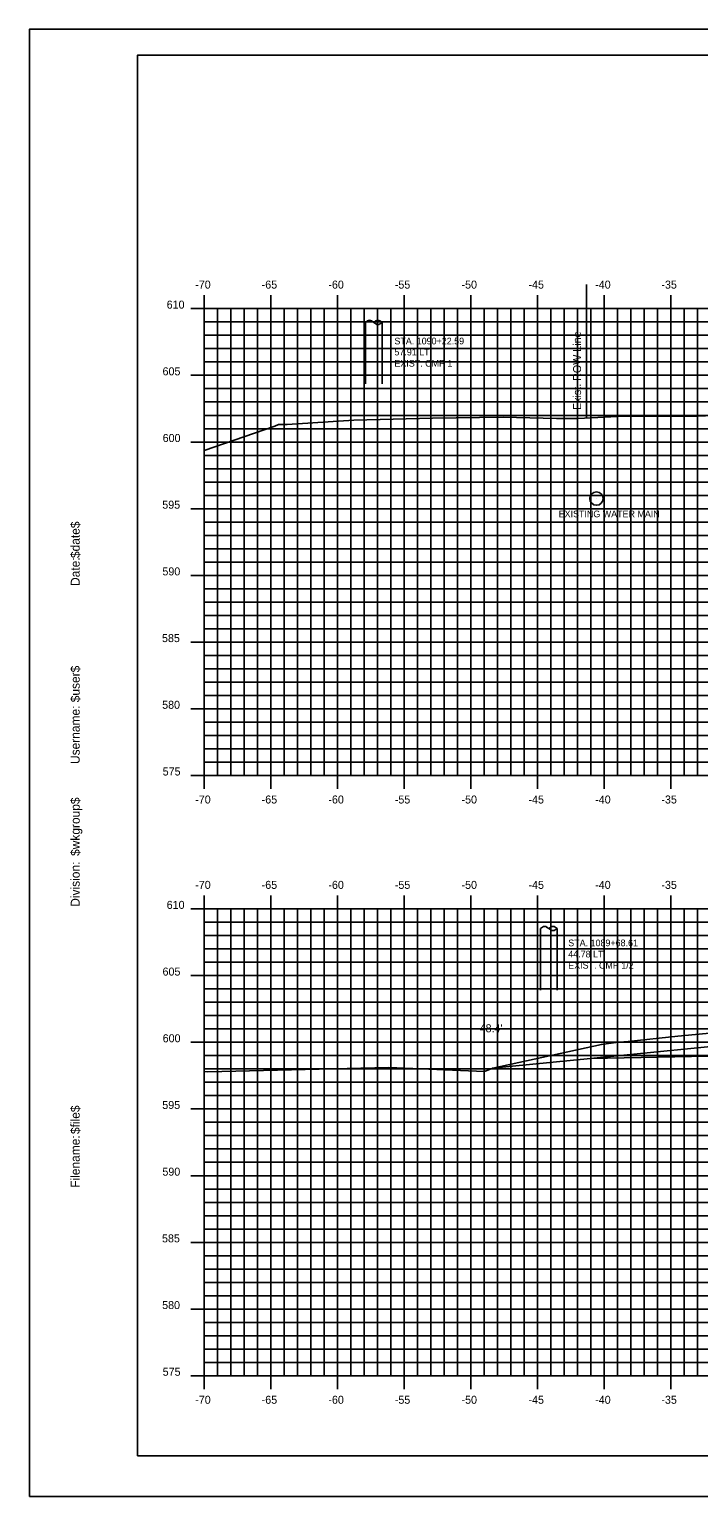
# Model space of a CAD drawing. Extents: x 1073421 to 1073591, y 779716 to 779826.
# Drawn here: x 1073420.9 to 1073471, y 779715.6 to 779825.6 of the extents above; entities that cross this region are included whole.
import ezdxf

# ---------------------------------------------------------------- set-up
doc = ezdxf.new("R2010")
doc.units = 0
for name, color, linetype in [('BORDER', 7, 'Continuous'), ('D_Roadway_SlopeLines', 7, 'Continuous'), ('D_Roadway_SubGrade', 7, 'Continuous'), ('D_Text_Monospaced', 7, 'Continuous'), ('D_Text_Standard', 7, 'Continuous'), ('E_ROW_Line', 7, 'Continuous'), ('Existing Water Main', 7, 'Continuous'), ('H_V ANNOTATION', 7, 'Continuous'), ('MAJOR', 7, 'Continuous'), ('MINOR', 7, 'Continuous'), ('PLOT BOUNDARY', 7, 'Continuous'), ('S_Roadway_Centerline', 7, 'Continuous'), ('S_Utilities_Pole_Joint', 7, 'Continuous'), ('S_Utilities_Pole_Power', 7, 'Continuous')]:
    doc.layers.add(name, color=color, linetype=linetype)

msp = doc.modelspace()

# ---------------------------------------------------------------- linework, layer by layer
at = {"layer": 'BORDER'}
msp.add_lwpolyline([(1073428.96, 779718.71), (1073588.96, 779718.71), (1073588.96, 779823.71), (1073428.96, 779823.71)], close=True, dxfattribs=at)
at = {"layer": 'D_Roadway_SlopeLines'}
msp.add_lwpolyline([(1073462.92, 779748.5), (1073455.55, 779747.76)], dxfattribs=at)
at = {"layer": 'D_Roadway_SubGrade'}
msp.add_lwpolyline([(1073491.96, 779750.83), (1073487.96, 779750.67), (1073487.96, 779751), (1073462.92, 779748.5), (1073491.96, 779749.08), (1073491.96, 779750.83)], close=True, dxfattribs=at)
at = {"layer": 'E_ROW_Line'}
msp.add_line((1073462.62, 779796.51), (1073462.62, 779806.51), dxfattribs=at)
msp.add_line((1073462.62, 779796.51), (1073462.62, 779806.51), dxfattribs=at)
at = {"layer": 'Existing Water Main'}
msp.add_lwpolyline([(1073463.37, 779790.47), (1073463.37, 779790.47)], dxfattribs=at)
msp.add_circle((1073463.37, 779790.47), 0.501, dxfattribs=at)
at = {"layer": 'MAJOR'}
for p, q in [((1073433.96, 779805.71), (1073433.96, 779804.71)), ((1073438.96, 779805.71), (1073438.96, 779804.71)), ((1073443.96, 779805.71), (1073443.96, 779804.71)), ((1073448.96, 779805.71), (1073448.96, 779804.71)), ((1073453.96, 779805.71), (1073453.96, 779804.71)), ((1073458.96, 779805.71), (1073458.96, 779804.71)), ((1073463.96, 779805.71), (1073463.96, 779804.71)), ((1073468.96, 779805.71), (1073468.96, 779804.71)), ((1073432.96, 779804.71), (1073433.96, 779804.71)), ((1073433.96, 779804.71), (1073573.96, 779804.71)), ((1073433.96, 779769.71), (1073433.96, 779804.71)), ((1073433.96, 779769.71), (1073433.96, 779804.71)), ((1073433.96, 779804.71), (1073573.96, 779804.71)), ((1073438.96, 779769.71), (1073438.96, 779804.71)), ((1073443.96, 779769.71), (1073443.96, 779804.71)), ((1073448.96, 779769.71), (1073448.96, 779804.71)), ((1073453.96, 779769.71), (1073453.96, 779804.71)), ((1073458.96, 779769.71), (1073458.96, 779804.71)), ((1073463.96, 779769.71), (1073463.96, 779804.71)), ((1073468.96, 779769.71), (1073468.96, 779804.71)), ((1073432.96, 779799.71), (1073433.96, 779799.71)), ((1073433.96, 779799.71), (1073573.96, 779799.71)), ((1073432.96, 779794.71), (1073433.96, 779794.71)), ((1073433.96, 779794.71), (1073573.96, 779794.71)), ((1073432.96, 779789.71), (1073433.96, 779789.71)), ((1073433.96, 779789.71), (1073573.96, 779789.71)), ((1073432.96, 779784.71), (1073433.96, 779784.71)), ((1073433.96, 779784.71), (1073573.96, 779784.71)), ((1073432.96, 779779.71), (1073433.96, 779779.71)), ((1073433.96, 779779.71), (1073573.96, 779779.71)), ((1073432.96, 779774.71), (1073433.96, 779774.71)), ((1073433.96, 779774.71), (1073573.96, 779774.71)), ((1073432.96, 779769.71), (1073433.96, 779769.71)), ((1073433.96, 779769.71), (1073573.96, 779769.71)), ((1073433.96, 779769.71), (1073573.96, 779769.71)), ((1073433.96, 779768.7), (1073433.96, 779769.71)), ((1073438.96, 779768.7), (1073438.96, 779769.71)), ((1073443.96, 779768.7), (1073443.96, 779769.71)), ((1073448.96, 779768.7), (1073448.96, 779769.71)), ((1073453.96, 779768.7), (1073453.96, 779769.71)), ((1073458.96, 779768.7), (1073458.96, 779769.71)), ((1073463.96, 779768.7), (1073463.96, 779769.71)), ((1073468.96, 779768.7), (1073468.96, 779769.71)), ((1073433.96, 779760.71), (1073433.96, 779759.71)), ((1073438.96, 779760.71), (1073438.96, 779759.71)), ((1073443.96, 779760.71), (1073443.96, 779759.71)), ((1073448.96, 779760.71), (1073448.96, 779759.71)), ((1073453.96, 779760.71), (1073453.96, 779759.71)), ((1073458.96, 779760.71), (1073458.96, 779759.71)), ((1073463.96, 779760.71), (1073463.96, 779759.71)), ((1073468.96, 779760.71), (1073468.96, 779759.71)), ((1073432.96, 779759.71), (1073433.96, 779759.71)), ((1073433.96, 779759.71), (1073573.96, 779759.71)), ((1073433.96, 779724.71), (1073433.96, 779759.71)), ((1073433.96, 779724.71), (1073433.96, 779759.71)), ((1073433.96, 779759.71), (1073573.96, 779759.71)), ((1073438.96, 779724.71), (1073438.96, 779759.71)), ((1073443.96, 779724.71), (1073443.96, 779759.71)), ((1073448.96, 779724.71), (1073448.96, 779759.71)), ((1073453.96, 779724.71), (1073453.96, 779759.71)), ((1073458.96, 779724.71), (1073458.96, 779759.71)), ((1073463.96, 779724.71), (1073463.96, 779759.71)), ((1073468.96, 779724.71), (1073468.96, 779759.71)), ((1073432.96, 779754.71), (1073433.96, 779754.71)), ((1073433.96, 779754.71), (1073573.96, 779754.71)), ((1073432.96, 779749.71), (1073433.96, 779749.71)), ((1073433.96, 779749.71), (1073573.96, 779749.71)), ((1073432.96, 779744.71), (1073433.96, 779744.71)), ((1073433.96, 779744.71), (1073573.96, 779744.71)), ((1073432.96, 779739.71), (1073433.96, 779739.71)), ((1073433.96, 779739.71), (1073573.96, 779739.71)), ((1073432.96, 779734.71), (1073433.96, 779734.71)), ((1073433.96, 779734.71), (1073573.96, 779734.71)), ((1073432.96, 779729.71), (1073433.96, 779729.71)), ((1073433.96, 779729.71), (1073573.96, 779729.71)), ((1073432.96, 779724.71), (1073433.96, 779724.71)), ((1073433.96, 779724.71), (1073573.96, 779724.71)), ((1073433.96, 779724.71), (1073573.96, 779724.71)), ((1073433.96, 779723.7), (1073433.96, 779724.71)), ((1073438.96, 779723.7), (1073438.96, 779724.71)), ((1073443.96, 779723.7), (1073443.96, 779724.71)), ((1073448.96, 779723.7), (1073448.96, 779724.71)), ((1073453.96, 779723.7), (1073453.96, 779724.71)), ((1073458.96, 779723.7), (1073458.96, 779724.71)), ((1073463.96, 779723.7), (1073463.96, 779724.71)), ((1073468.96, 779723.7), (1073468.96, 779724.71))]:
    msp.add_line(p, q, dxfattribs=at)
at = {"layer": 'MINOR'}
for p, q in [((1073434.96, 779769.71), (1073434.96, 779804.71)), ((1073435.96, 779769.71), (1073435.96, 779804.71)), ((1073436.96, 779769.71), (1073436.96, 779804.71)), ((1073437.96, 779769.71), (1073437.96, 779804.71)), ((1073439.96, 779769.71), (1073439.96, 779804.71)), ((1073440.96, 779769.71), (1073440.96, 779804.71)), ((1073441.96, 779769.71), (1073441.96, 779804.71)), ((1073442.96, 779769.71), (1073442.96, 779804.71)), ((1073444.96, 779769.71), (1073444.96, 779804.71)), ((1073445.96, 779769.71), (1073445.96, 779804.71)), ((1073446.96, 779769.71), (1073446.96, 779804.71)), ((1073447.96, 779769.71), (1073447.96, 779804.71)), ((1073449.96, 779769.71), (1073449.96, 779804.71)), ((1073450.96, 779769.71), (1073450.96, 779804.71)), ((1073451.96, 779769.71), (1073451.96, 779804.71)), ((1073452.96, 779769.71), (1073452.96, 779804.71)), ((1073454.96, 779769.71), (1073454.96, 779804.71)), ((1073455.96, 779769.71), (1073455.96, 779804.71)), ((1073456.96, 779769.71), (1073456.96, 779804.71)), ((1073457.96, 779769.71), (1073457.96, 779804.71)), ((1073459.96, 779769.71), (1073459.96, 779804.71)), ((1073460.96, 779769.71), (1073460.96, 779804.71)), ((1073461.96, 779769.71), (1073461.96, 779804.71)), ((1073462.96, 779769.71), (1073462.96, 779804.71)), ((1073464.96, 779769.71), (1073464.96, 779804.71)), ((1073465.96, 779769.71), (1073465.96, 779804.71)), ((1073466.96, 779769.71), (1073466.96, 779804.71)), ((1073467.96, 779769.71), (1073467.96, 779804.71)), ((1073469.96, 779769.71), (1073469.96, 779804.71)), ((1073470.96, 779769.71), (1073470.96, 779804.71)), ((1073433.96, 779803.71), (1073573.96, 779803.71)), ((1073433.96, 779803.71), (1073434.96, 779803.71)), ((1073433.96, 779802.71), (1073573.96, 779802.71)), ((1073433.96, 779802.71), (1073434.96, 779802.71)), ((1073433.96, 779801.71), (1073573.96, 779801.71)), ((1073433.96, 779801.71), (1073434.96, 779801.71)), ((1073433.96, 779800.71), (1073573.96, 779800.71)), ((1073433.96, 779800.71), (1073434.96, 779800.71)), ((1073433.96, 779798.71), (1073573.96, 779798.71)), ((1073433.96, 779798.71), (1073434.96, 779798.71)), ((1073433.96, 779797.71), (1073573.96, 779797.71)), ((1073433.96, 779797.71), (1073434.96, 779797.71)), ((1073433.96, 779796.71), (1073573.96, 779796.71)), ((1073433.96, 779796.71), (1073434.96, 779796.71)), ((1073433.96, 779795.71), (1073573.96, 779795.71)), ((1073433.96, 779795.71), (1073434.96, 779795.71)), ((1073433.96, 779793.71), (1073573.96, 779793.71)), ((1073433.96, 779793.71), (1073434.96, 779793.71)), ((1073433.96, 779792.71), (1073573.96, 779792.71)), ((1073433.96, 779792.71), (1073434.96, 779792.71)), ((1073433.96, 779791.71), (1073573.96, 779791.71)), ((1073433.96, 779791.71), (1073434.96, 779791.71)), ((1073433.96, 779790.71), (1073573.96, 779790.71)), ((1073433.96, 779790.71), (1073434.96, 779790.71)), ((1073433.96, 779788.71), (1073573.96, 779788.71)), ((1073433.96, 779788.71), (1073434.96, 779788.71)), ((1073433.96, 779787.71), (1073573.96, 779787.71)), ((1073433.96, 779787.71), (1073434.96, 779787.71)), ((1073433.96, 779786.71), (1073573.96, 779786.71)), ((1073433.96, 779786.71), (1073434.96, 779786.71)), ((1073433.96, 779785.71), (1073573.96, 779785.71)), ((1073433.96, 779785.71), (1073434.96, 779785.71)), ((1073433.96, 779783.71), (1073573.96, 779783.71)), ((1073433.96, 779783.71), (1073434.96, 779783.71)), ((1073433.96, 779782.71), (1073573.96, 779782.71)), ((1073433.96, 779782.71), (1073434.96, 779782.71)), ((1073433.96, 779781.71), (1073573.96, 779781.71)), ((1073433.96, 779781.71), (1073434.96, 779781.71)), ((1073433.96, 779780.71), (1073573.96, 779780.71)), ((1073433.96, 779780.71), (1073434.96, 779780.71)), ((1073433.96, 779778.71), (1073573.96, 779778.71)), ((1073433.96, 779778.71), (1073434.96, 779778.71)), ((1073433.96, 779777.71), (1073573.96, 779777.71)), ((1073433.96, 779777.71), (1073434.96, 779777.71)), ((1073433.96, 779776.71), (1073573.96, 779776.71)), ((1073433.96, 779776.71), (1073434.96, 779776.71)), ((1073433.96, 779775.71), (1073573.96, 779775.71)), ((1073433.96, 779775.71), (1073434.96, 779775.71)), ((1073433.96, 779773.71), (1073573.96, 779773.71)), ((1073433.96, 779773.71), (1073434.96, 779773.71)), ((1073433.96, 779772.71), (1073573.96, 779772.71)), ((1073433.96, 779772.71), (1073434.96, 779772.71)), ((1073433.96, 779771.71), (1073573.96, 779771.71)), ((1073433.96, 779771.71), (1073434.96, 779771.71)), ((1073433.96, 779770.71), (1073573.96, 779770.71)), ((1073433.96, 779770.71), (1073434.96, 779770.71)), ((1073434.96, 779724.71), (1073434.96, 779759.71)), ((1073435.96, 779724.71), (1073435.96, 779759.71)), ((1073436.96, 779724.71), (1073436.96, 779759.71)), ((1073437.96, 779724.71), (1073437.96, 779759.71)), ((1073439.96, 779724.71), (1073439.96, 779759.71)), ((1073440.96, 779724.71), (1073440.96, 779759.71)), ((1073441.96, 779724.71), (1073441.96, 779759.71)), ((1073442.96, 779724.71), (1073442.96, 779759.71)), ((1073444.96, 779724.71), (1073444.96, 779759.71)), ((1073445.96, 779724.71), (1073445.96, 779759.71)), ((1073446.96, 779724.71), (1073446.96, 779759.71)), ((1073447.96, 779724.71), (1073447.96, 779759.71)), ((1073449.96, 779724.71), (1073449.96, 779759.71)), ((1073450.96, 779724.71), (1073450.96, 779759.71)), ((1073451.96, 779724.71), (1073451.96, 779759.71)), ((1073452.96, 779724.71), (1073452.96, 779759.71)), ((1073454.96, 779724.71), (1073454.96, 779759.71)), ((1073455.96, 779724.71), (1073455.96, 779759.71)), ((1073456.96, 779724.71), (1073456.96, 779759.71)), ((1073457.96, 779724.71), (1073457.96, 779759.71)), ((1073459.96, 779724.71), (1073459.96, 779759.71)), ((1073460.96, 779724.71), (1073460.96, 779759.71)), ((1073461.96, 779724.71), (1073461.96, 779759.71)), ((1073462.96, 779724.71), (1073462.96, 779759.71)), ((1073464.96, 779724.71), (1073464.96, 779759.71)), ((1073465.96, 779724.71), (1073465.96, 779759.71)), ((1073466.96, 779724.71), (1073466.96, 779759.71)), ((1073467.96, 779724.71), (1073467.96, 779759.71)), ((1073469.96, 779724.71), (1073469.96, 779759.71)), ((1073470.96, 779724.71), (1073470.96, 779759.71)), ((1073433.96, 779758.71), (1073573.96, 779758.71)), ((1073433.96, 779758.71), (1073434.96, 779758.71)), ((1073433.96, 779757.71), (1073573.96, 779757.71)), ((1073433.96, 779757.71), (1073434.96, 779757.71)), ((1073433.96, 779756.71), (1073573.96, 779756.71)), ((1073433.96, 779756.71), (1073434.96, 779756.71)), ((1073433.96, 779755.71), (1073573.96, 779755.71)), ((1073433.96, 779755.71), (1073434.96, 779755.71)), ((1073433.96, 779753.71), (1073573.96, 779753.71)), ((1073433.96, 779753.71), (1073434.96, 779753.71)), ((1073433.96, 779752.71), (1073573.96, 779752.71)), ((1073433.96, 779752.71), (1073434.96, 779752.71)), ((1073433.96, 779751.71), (1073573.96, 779751.71)), ((1073433.96, 779751.71), (1073434.96, 779751.71)), ((1073433.96, 779750.71), (1073573.96, 779750.71)), ((1073433.96, 779750.71), (1073434.96, 779750.71)), ((1073433.96, 779748.71), (1073573.96, 779748.71)), ((1073433.96, 779748.71), (1073434.96, 779748.71)), ((1073433.96, 779747.71), (1073573.96, 779747.71)), ((1073433.96, 779747.71), (1073434.96, 779747.71)), ((1073433.96, 779746.71), (1073573.96, 779746.71)), ((1073433.96, 779746.71), (1073434.96, 779746.71)), ((1073433.96, 779745.71), (1073573.96, 779745.71)), ((1073433.96, 779745.71), (1073434.96, 779745.71)), ((1073433.96, 779743.71), (1073573.96, 779743.71)), ((1073433.96, 779743.71), (1073434.96, 779743.71)), ((1073433.96, 779742.71), (1073573.96, 779742.71)), ((1073433.96, 779742.71), (1073434.96, 779742.71)), ((1073433.96, 779741.71), (1073573.96, 779741.71)), ((1073433.96, 779741.71), (1073434.96, 779741.71)), ((1073433.96, 779740.71), (1073573.96, 779740.71)), ((1073433.96, 779740.71), (1073434.96, 779740.71)), ((1073433.96, 779738.71), (1073573.96, 779738.71)), ((1073433.96, 779738.71), (1073434.96, 779738.71)), ((1073433.96, 779737.71), (1073573.96, 779737.71)), ((1073433.96, 779737.71), (1073434.96, 779737.71)), ((1073433.96, 779736.71), (1073573.96, 779736.71)), ((1073433.96, 779736.71), (1073434.96, 779736.71)), ((1073433.96, 779735.71), (1073573.96, 779735.71)), ((1073433.96, 779735.71), (1073434.96, 779735.71)), ((1073433.96, 779733.71), (1073573.96, 779733.71)), ((1073433.96, 779733.71), (1073434.96, 779733.71)), ((1073433.96, 779732.71), (1073573.96, 779732.71)), ((1073433.96, 779732.71), (1073434.96, 779732.71)), ((1073433.96, 779731.71), (1073573.96, 779731.71)), ((1073433.96, 779731.71), (1073434.96, 779731.71)), ((1073433.96, 779730.71), (1073573.96, 779730.71)), ((1073433.96, 779730.71), (1073434.96, 779730.71)), ((1073433.96, 779728.71), (1073573.96, 779728.71)), ((1073433.96, 779728.71), (1073434.96, 779728.71)), ((1073433.96, 779727.71), (1073573.96, 779727.71)), ((1073433.96, 779727.71), (1073434.96, 779727.71)), ((1073433.96, 779726.71), (1073573.96, 779726.71)), ((1073433.96, 779726.71), (1073434.96, 779726.71)), ((1073433.96, 779725.71), (1073573.96, 779725.71)), ((1073433.96, 779725.71), (1073434.96, 779725.71))]:
    msp.add_line(p, q, dxfattribs=at)
at = {"layer": 'PLOT BOUNDARY'}
msp.add_lwpolyline([(1073420.87, 779715.65), (1073590.87, 779715.65), (1073590.87, 779825.65), (1073420.87, 779825.65)], close=True, dxfattribs=at)
at = {"layer": 'S_Roadway_Centerline'}
for points in [[(1073433.96, 779794.08), (1073439.27, 779795.9), (1073439.53, 779796.02), (1073440.18, 779796.02), (1073445.19, 779796.34), (1073451.08, 779796.51), (1073456.39, 779796.58), (1073460.38, 779796.48), (1073461.97, 779796.48), (1073465.44, 779796.66), (1073470.88, 779796.64), (1073477.74, 779796.91)], [(1073433.96, 779747.52), (1073434.25, 779747.5), (1073447.81, 779747.82), (1073454.98, 779747.51), (1073455.61, 779747.78), (1073463.74, 779749.55), (1073464.83, 779749.69), (1073465.11, 779749.71), (1073465.76, 779749.76), (1073469.48, 779750.18), (1073473.45, 779750.55)]]:
    msp.add_lwpolyline(points, dxfattribs=at)
at = {"layer": 'S_Utilities_Pole_Joint'}
for p, q in [((1073446.05, 779803.68), (1073446.21, 779803.79)), ((1073446.52, 779803.79), (1073446.68, 779803.68)), ((1073446.83, 779803.79), (1073446.68, 779803.68)), ((1073446.68, 779803.68), (1073446.83, 779803.57)), ((1073447.3, 779803.68), (1073447.15, 779803.79)), ((1073447.15, 779803.57), (1073447.3, 779803.68)), ((1073459.18, 779758.24), (1073459.33, 779758.35)), ((1073459.64, 779758.35), (1073459.8, 779758.24)), ((1073459.96, 779758.35), (1073459.8, 779758.24)), ((1073459.8, 779758.24), (1073459.96, 779758.13)), ((1073460.43, 779758.24), (1073460.27, 779758.35)), ((1073460.27, 779758.13), (1073460.43, 779758.24))]:
    msp.add_line(p, q, dxfattribs=at)
for centre, start, end in [((1073446.36, 779803.57), 90, 125.2644), ((1073446.36, 779803.57), 54.7356, 90), ((1073446.99, 779803.57), 90, 125.2644), ((1073446.99, 779803.79), 234.7356, 270), ((1073446.99, 779803.57), 54.7356, 90), ((1073446.99, 779803.79), 270, 305.2644), ((1073459.49, 779758.13), 90, 125.2644), ((1073459.49, 779758.13), 54.7356, 90), ((1073460.11, 779758.13), 90, 125.2644), ((1073460.11, 779758.35), 234.7356, 270), ((1073460.11, 779758.13), 54.7356, 90), ((1073460.11, 779758.35), 270, 305.2644)]:
    msp.add_arc(centre, 0.271, start, end, dxfattribs=at)
at = {"layer": 'S_Utilities_Pole_Power'}
for p, q in [((1073446.05, 779799.06), (1073446.05, 779803.68)), ((1073447.3, 779799.06), (1073447.3, 779803.68)), ((1073459.18, 779753.62), (1073459.17, 779758.24)), ((1073460.43, 779753.62), (1073460.42, 779758.24))]:
    msp.add_line(p, q, dxfattribs=at)

# ---------------------------------------------------------------- texts
at = {"layer": 'BORDER'}
for s, p in [('$date$', (1073424.64, 779786.01)), ('Date:', (1073424.64, 779783.92)), ('$user$', (1073424.64, 779775.2)), ('Username:', (1073424.64, 779770.57)), ('$wkgroup$', (1073424.64, 779763.68)), ('Division:', (1073424.64, 779759.87)), ('$file$', (1073424.64, 779742.83)), ('Filename:', (1073424.64, 779738.8))]:
    msp.add_text(s, height=0.67, rotation=90, dxfattribs=at).set_placement(p)
at = {"layer": 'D_Text_Monospaced'}
for s, p in [('STA. 1090+22.59', (1073448.23, 779802.03)), ('57.91 LT.', (1073448.23, 779801.2)), ('EXIST. CMP 1', (1073448.23, 779800.36)), ('EXISTING WATER MAIN', (1073460.54, 779789.07)), ('STA. 1089+68.61', (1073461.26, 779756.91)), ('44.78 LT.', (1073461.26, 779756.07)), ('EXIST. CMP 1/2', (1073461.26, 779755.23))]:
    msp.add_text(s, height=0.5, dxfattribs=at).set_placement(p)
at = {"layer": 'D_Text_Standard'}
msp.add_text("-48.4'", height=0.6, dxfattribs=at).set_placement((1073454.35, 779750.46))
at = {"layer": 'E_ROW_Line'}
msp.add_text('Exist. ROW Line', height=0.6, rotation=90, dxfattribs=at).set_placement((1073462.22, 779797.11))
at = {"layer": 'H_V ANNOTATION'}
for s, p in [('-70', (1073433.3, 779806.21)), ('-65', (1073438.28, 779806.21)), ('-60', (1073443.28, 779806.21)), ('-55', (1073448.26, 779806.21)), ('-50', (1073453.26, 779806.21)), ('-45', (1073458.28, 779806.21)), ('-40', (1073463.28, 779806.21)), ('-35', (1073468.24, 779806.21)), ('610', (1073431.16, 779804.71)), ('605', (1073430.85, 779799.71)), ('600', (1073430.86, 779794.71)), ('595', (1073430.83, 779789.71)), ('590', (1073430.84, 779784.71)), ('585', (1073430.81, 779779.71)), ('580', (1073430.82, 779774.71)), ('575', (1073430.86, 779769.71)), ('-70', (1073433.3, 779767.61)), ('-65', (1073438.28, 779767.61)), ('-60', (1073443.28, 779767.61)), ('-55', (1073448.26, 779767.61)), ('-50', (1073453.26, 779767.61)), ('-45', (1073458.28, 779767.61)), ('-40', (1073463.28, 779767.61)), ('-35', (1073468.24, 779767.61)), ('-70', (1073433.3, 779761.21)), ('-65', (1073438.28, 779761.21)), ('-60', (1073443.28, 779761.21)), ('-55', (1073448.26, 779761.21)), ('-50', (1073453.26, 779761.21)), ('-45', (1073458.28, 779761.21)), ('-40', (1073463.28, 779761.21)), ('-35', (1073468.24, 779761.21)), ('610', (1073431.16, 779759.71)), ('605', (1073430.85, 779754.71)), ('600', (1073430.86, 779749.71)), ('595', (1073430.83, 779744.71)), ('590', (1073430.84, 779739.71)), ('585', (1073430.81, 779734.71)), ('580', (1073430.82, 779729.71)), ('575', (1073430.86, 779724.71)), ('-70', (1073433.3, 779722.61)), ('-65', (1073438.28, 779722.61)), ('-60', (1073443.28, 779722.61)), ('-55', (1073448.26, 779722.61)), ('-50', (1073453.26, 779722.61)), ('-45', (1073458.28, 779722.61)), ('-40', (1073463.28, 779722.61)), ('-35', (1073468.24, 779722.61))]:
    msp.add_text(s, height=0.6, dxfattribs=at).set_placement(p)
at = {"layer": 'MAJOR'}
for p in [(1073433.95, 779769.71), (1073433.95, 779724.71)]:
    msp.add_text('-', height=0.006, dxfattribs=at).set_placement(p)

doc.saveas('drawing.dxf')
